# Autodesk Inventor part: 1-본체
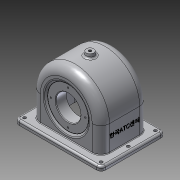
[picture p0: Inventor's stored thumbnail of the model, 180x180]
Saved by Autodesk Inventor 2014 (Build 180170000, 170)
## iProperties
Created: 2015-09
Part Number: 1-본체
Material: 알루미늄 6061
Document SubType Name: Modeling
Designer: Administrator
Density: 2.71 g/cm^3
Appearance: 알루미늄 - 평지
Mass: 736.144 g
Surface Area: 880.74 cm^2
Volume: 271.64 cm^3
Author: Administrator
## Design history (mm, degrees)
sketch "스케치1"
  geometry: L1 (-70, 52)-(70, 52); L2 (70, 52)-(70, -52); L3 (70, -52)-(-70, -52); L4 (-70, -52)-(-70, 52); 3 further points
  constraints: 8 end point, 2 midpoint, 2 parallel, 1 horizontal, 1 horizontal alignment, 1 perpendicular, 1 vertical alignment
  dimensions: "d0" = 104 distance of L1.end L2.end; "d1" = 140 distance of L2.end L3.end
extrude "돌출1" new body sketch "스케치1" distance "d2" = 7; taper "d3" = 0 deg
sketch "스케치2"
  geometry: L1 (-70, 0)-(70, 0) reference; L2 (-56, 48)-(-56, 0); L3 (-56, 0)-(56, 0); L4 (56, 0)-(56, 48); A1 r 56 centre (0, 48) between (-56, 48) and (56, 48); 2 further points
  constraints: 6 end point, 2 point on circle, 2 point on line, 2 tangent, 1 centre point, 1 midpoint, 1 perpendicular, 1 vertical, 1 vertical alignment
  dimensions: "d4" = 112 diameter of A1; "d7" = 104 dimension on A1 L1
extrude "돌출2" join sketch "스케치2" stored distance "d8" = 77; taper "d9" = 0 deg
sketch "스케치3"
  geometry: L1 (-70, 0)-(70, 0) reference; C1 r 31 at (0, -48); A1 r 56 centre (0, -48) between (-56, -48) and (56, -48) reference; 2 further points
  constraints: 1 centre point, 1 concentric, 1 midpoint, 1 vertical alignment
  dimensions: "d10" = 62 diameter of C1
sketch "스케치4"
  geometry: L1 (50, 48)-(50, 0); L2 (50, 0)-(-50, 0); L3 (-50, 0)-(-50, 48); L4 (70, 0)-(-70, 0) reference; A1 r 56 centre (0, 48) between (56, 48) and (-56, 48) reference; A2 r 50 centre (0, 48) between (50, 48) and (-50, 48); 1 further point
  constraints: 6 end point, 2 point on circle, 2 tangent, 1 centre point, 1 collinear, 1 parallel, 1 perpendicular, 1 vertical
  dimensions: "d11" = 6 radial gap between concentric circles of A1 A2
extrude "돌출3" cut sketch "스케치4" stored distance "d12" = 67; taper "d13" = 0 deg
sketch "스케치5"
  geometry: C1 r 31 at (0, -48); A1 r 56 centre (0, -48) between (-56, -48) and (56, -48) reference; 1 further point
  constraints: 1 centre point, 1 concentric
  dimensions: "d14" = 62 diameter of C1
extrude "돌출4" join sketch "스케치5" distance "d15" = 10; taper "d16" = 0 deg
sketch "스케치6"
  geometry: L1 (-10.456, 13.613)-(-10.456, 63.387); L2 (-10.456, 63.387)-(-35.544, 63.387); L3 (-35.544, 63.387)-(-35.544, 13.613); L4 (-35.544, 13.613)-(-10.456, 13.613); L5 (7, 90.5)-(7, -13.5) reference; 6 further points
  constraints: 4 midpoint, 1 horizontal alignment, 1 vertical alignment, 2 other
  dimensions: "d17" = 30 distance from line of L5 point (-23, 38.5)
feature "엠보싱1" sketch "스케치6" dims "d18" = 0.5, "d19" = 0
node "작업 평면1"
sketch "스케치7"
  geometry: C1 r 28 at (0, -48); A1 r 56 centre (0, -48) between (-56, -48) and (56, -48) reference; 1 further point
  constraints: 1 centre point, 1 concentric, 1 vertical alignment
  dimensions: "d21" = 56 diameter of C1
extrude "돌출5" join sketch "스케치7" stored distance "d22" = 10; taper "d23" = 40 deg
node "작업 평면2"
sketch "스케치8"
  geometry: C1 r 33 at (0, 48); A1 r 56 centre (0, 48) between (56, 48) and (-56, 48) reference; 1 further point
  constraints: 1 centre point, 1 concentric, 1 vertical alignment
  dimensions: "d25" = 66 diameter of C1
extrude "돌출6" cut sketch "스케치8" distance "d26" = 3; taper "d27" = 50 deg
hole "구멍1" diameter "d30" = 40; stored, may be unused: countersink angle "d34" = 90 deg, drill point angle "d36" = 0 deg; dims "d28" = 10, "d29" = 10, "d31" = 6, "d32" = 4, "d33" = 2, "d35" = 8
fillet "모깎기1" dims "d37" = 7
fillet "모깎기2" dims "d38" = 14
fillet "모깎기3" dims "d39" = 9
sketch "스케치9"
  geometry: L1 (0, 0)-(62, 0)
  constraints: 2 end point, 1 horizontal
  dimensions: "d40" = 62 distance of L1.start L1.end
hole "구멍2" sketch "스케치9" at (62, 0) diameter "d41" = 5; stored, may be unused: countersink angle "d45" = 90 deg, drill point angle "d47" = 0 deg; dims "d42" = 6, "d43" = 4, "d44" = 2, "d46" = 8
fillet "모깎기4" dims "d63" = 3
chamfer "모따기1" distance "d64" = 1; stored, may be unused: second distance "d65" = 2, angle "d66" = 45 deg
sketch "스케치10"
  geometry: 1 further point
node "작업 평면3"
sketch "스케치11"
  geometry: C1 r 6 at (0, 0); 1 further point
  constraints: 1 centre point, 1 coincident
  dimensions: "d68" = 12 diameter of C1
extrude "돌출7" join sketch "스케치11" stored distance "d69" = 3; taper "d70" = 10 deg
fillet "모깎기5" dims "d71" = 3
hole "구멍3" diameter "d74" = 4.459; stored, may be unused: countersink angle "d78" = 90 deg, drill point angle "d80" = 0 deg; dims "d75" = 15, "d76" = 4, "d77" = 2, "d79" = 8, "d106" = 10, "d107" = 10
fillet "모깎기6" dims "d81" = 0.5
sketch "스케치12"
  geometry: L1 (0, 0)-(0, 28); L2 (63, -48)-(-63, -48) reference; 2 further points
  constraints: 2 end point, 1 midpoint, 1 vertical, 1 vertical alignment
  dimensions: "d82" = 28 distance of L1.start L1.end; "d83" = 48 distance from line of L2 L1.start
hole "구멍4" sketch "스케치12" at (0, 28) diameter "d84" = 2.621; stored, may be unused: countersink angle "d88" = 90 deg, drill point angle "d90" = 120 deg; dims "d85" = 7, "d86" = 4, "d87" = 2, "d89" = 9
sketch "스케치13"
  geometry: L1 (0, 0)-(0, -24); L2 (-63, 48)-(63, 48) reference; 2 further points
  constraints: 2 end point, 1 midpoint, 1 vertical, 1 vertical alignment
  dimensions: "d94" = 48 distance from line of L2 L1.start; "d95" = 24 distance of L1.start L1.end
hole "구멍5" sketch "스케치13" at (0, -24) diameter "d96" = 2.621; stored, may be unused: countersink angle "d100" = 90 deg, drill point angle "d102" = 120 deg; dims "d97" = 6, "d98" = 4, "d99" = 2, "d101" = 8
fillet "모깎기7" dims "d108" = 1
node "솔리드1"
pattern_linear "직사각형 패턴1" dims "d50" = 124
pattern_linear "직사각형 패턴2" dims "d53" = 44, "d56" = 124
pattern_linear "직사각형 패턴3" dims "d59" = 44, "d62" = 124
pattern_circular "원형 패턴1" dims angle "d92" = 360 deg
pattern_circular "원형 패턴2" dims angle "d104" = 360 deg
other parameters: "d20" = 15, "d24" = -3
